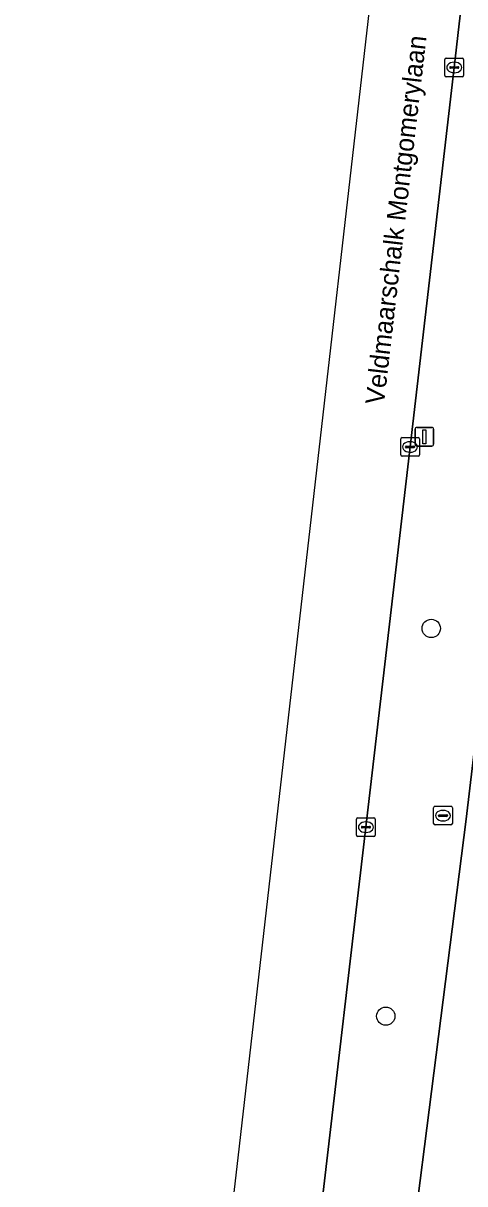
# Model space of a CAD drawing. Extents: x 161241 to 161758, y 384138 to 384885.
# Drawn here: x 161277.3 to 161300.9, y 384572 to 384634 of the extents above; entities that cross this region are included whole.
import ezdxf

# ---------------------------------------------------------------- set-up
doc = ezdxf.new("R2010")
doc.units = 0
for name, color, linetype in [('IMGEO_Berm_groen', 7, 'Continuous'), ('IMGEO_Boom', 7, 'Continuous'), ('IMGEO_Fietspad_gesloten', 7, 'Continuous'), ('IMGEO_Kolk', 7, 'Continuous'), ('IMGEO_Lichtmast', 7, 'Continuous'), ('IMGEO_Openbare_ruimte_label', 7, 'Continuous'), ('IMGEO_OVBaan_gesloten', 7, 'Continuous'), ('IMGEO_Rioolput', 7, 'Continuous')]:
    doc.layers.add(name, color=color, linetype=linetype)

msp = doc.modelspace()

# ---------------------------------------------------------------- linework, layer by layer
at = {"layer": 'IMGEO_Berm_groen'}
msp.add_lwpolyline([(161278.307, 384403.15), (161286.202, 384471.417), (161293.323, 384531.813), (161296.311, 384554.647), (161300.999, 384591.473), (161306.453, 384637.728), (161301.117, 384638.364), (161300.355, 384631.67), (161297.994, 384611.38), (161295.634, 384591.049), (161293.255, 384570.775), (161290.848, 384550.464), (161288.707, 384532.15), (161288.472, 384530.133), (161286.341, 384511.851), (161283.768, 384490.025), (161281.583, 384471.698), (161279.185, 384451.364)], dxfattribs=at)
at = {"layer": 'IMGEO_Boom'}
for centre in [(161299.125, 384601.675), (161296.698, 384580.943)]:
    msp.add_circle(centre, 0.489, dxfattribs=at)
at = {"layer": 'IMGEO_Fietspad_gesloten'}
msp.add_lwpolyline([(161308.263, 384652.525), (161306.453, 384637.728), (161300.999, 384591.473), (161296.311, 384554.647), (161293.323, 384531.813), (161286.202, 384471.417), (161278.307, 384403.15), (161275.866, 384382.258), (161272.845, 384356.399), (161269.542, 384328.133), (161269.524, 384327.978), (161266.559, 384302.554), (161265.412, 384302.67), (161262.065, 384303.024), (161261.777, 384300.445), (161262.272, 384300.399), (161264.329, 384300.231)], dxfattribs=at)
at = {"layer": 'IMGEO_Kolk'}
for p, q in [((161299.854, 384631.244), (161299.854, 384632.096)), ((161299.929, 384632.17), (161300.781, 384632.17)), ((161300.855, 384632.096), (161300.855, 384631.244)), ((161300.113, 384631.664), (161300.113, 384631.676)), ((161300.551, 384631.627), (161300.153, 384631.627)), ((161300.156, 384631.713), (161300.554, 384631.713)), ((161300.342, 384631.95), (161300.367, 384631.95)), ((161300.597, 384631.676), (161300.597, 384631.664)), ((161300.781, 384631.17), (161299.929, 384631.17)), ((161300.365, 384631.39), (161300.34, 384631.39)), ((161297.493, 384610.954), (161297.493, 384611.806)), ((161297.568, 384611.88), (161298.42, 384611.88)), ((161297.981, 384611.66), (161298.006, 384611.66)), ((161298.494, 384611.806), (161298.494, 384610.954)), ((161297.752, 384611.374), (161297.752, 384611.386)), ((161298.19, 384611.337), (161297.792, 384611.337)), ((161297.795, 384611.423), (161298.193, 384611.423)), ((161298.004, 384611.1), (161297.979, 384611.1)), ((161298.236, 384611.386), (161298.236, 384611.374)), ((161298.42, 384610.88), (161297.568, 384610.88)), ((161295.133, 384590.623), (161295.133, 384591.475)), ((161295.208, 384591.549), (161296.06, 384591.549)), ((161295.621, 384591.329), (161295.646, 384591.329)), ((161296.134, 384591.475), (161296.134, 384590.623)), ((161296.06, 384590.549), (161295.208, 384590.549)), ((161295.392, 384591.043), (161295.392, 384591.055)), ((161295.83, 384591.006), (161295.432, 384591.006)), ((161295.435, 384591.092), (161295.833, 384591.092)), ((161295.644, 384590.769), (161295.619, 384590.769)), ((161295.876, 384591.055), (161295.876, 384591.043))]:
    msp.add_line(p, q, dxfattribs=at)
for points in [[(161299.854, 384631.244), (161299.854, 384632.096)], [(161299.929, 384632.17), (161300.781, 384632.17)], [(161300.855, 384632.096), (161300.855, 384631.244)], [(161300.781, 384631.17), (161299.929, 384631.17)], [(161297.493, 384610.954), (161297.493, 384611.806)], [(161297.568, 384611.88), (161298.42, 384611.88)], [(161298.494, 384611.806), (161298.494, 384610.954)], [(161298.42, 384610.88), (161297.568, 384610.88)], [(161295.133, 384590.623), (161295.133, 384591.475)], [(161295.208, 384591.549), (161296.06, 384591.549)], [(161296.134, 384591.475), (161296.134, 384590.623)], [(161296.06, 384590.549), (161295.208, 384590.549)]]:
    msp.add_lwpolyline(points, dxfattribs=at)
for centre, radius, start, end in [((161299.931, 384632.094), 0.0765, 91.55205, 178.44795), ((161299.931, 384632.094), 0.0765, 91.55205, 178.44795), ((161300.779, 384632.094), 0.0765, 1.55205, 88.44795), ((161300.779, 384632.094), 0.0765, 1.55205, 88.44795), ((161300.153, 384631.673), 0.0403, 85.87752, 175.75265), ((161300.15, 384631.663), 0.0366, 178.93798, 274.71019), ((161300.554, 384631.67), 0.043, 264.86636, 352.45326), ((161300.558, 384631.675), 0.0386, 1.73085, 96.63898), ((161299.931, 384631.246), 0.0765, 181.55205, 268.44795), ((161299.931, 384631.246), 0.0765, 181.55205, 268.44795), ((161300.779, 384631.246), 0.0765, 271.55205, 358.44795), ((161300.779, 384631.246), 0.0765, 271.55205, 358.44795), ((161297.57, 384611.804), 0.0765, 91.55205, 178.44795), ((161297.57, 384611.804), 0.0765, 91.55205, 178.44795), ((161298.418, 384611.804), 0.0765, 1.55205, 88.44795), ((161298.418, 384611.804), 0.0765, 1.55205, 88.44795), ((161297.792, 384611.383), 0.0403, 85.87752, 175.75265), ((161297.789, 384611.373), 0.0366, 178.93798, 274.71019), ((161298.193, 384611.38), 0.043, 264.86636, 352.45326), ((161298.197, 384611.385), 0.0386, 1.73085, 96.63898), ((161297.57, 384610.956), 0.0765, 181.55205, 268.44795), ((161297.57, 384610.956), 0.0765, 181.55205, 268.44795), ((161298.418, 384610.956), 0.0765, 271.55205, 358.44795), ((161298.418, 384610.956), 0.0765, 271.55205, 358.44795), ((161295.21, 384591.473), 0.0765, 91.55205, 178.44795), ((161295.21, 384591.473), 0.0765, 91.55205, 178.44795), ((161296.058, 384591.473), 0.0765, 1.55205, 88.44795), ((161296.058, 384591.473), 0.0765, 1.55205, 88.44795), ((161295.21, 384590.625), 0.0765, 181.55205, 268.44795), ((161295.21, 384590.625), 0.0765, 181.55205, 268.44795), ((161295.432, 384591.052), 0.0403, 85.87752, 175.75265), ((161295.429, 384591.042), 0.0366, 178.93798, 274.71019), ((161295.833, 384591.049), 0.043, 264.86636, 352.45326), ((161295.837, 384591.054), 0.0386, 1.73085, 96.63898), ((161296.058, 384590.625), 0.0765, 271.55205, 358.44795), ((161296.058, 384590.625), 0.0765, 271.55205, 358.44795)]:
    msp.add_arc(centre, radius, start, end, dxfattribs=at)
for centre, major_axis, ratio, start_param, end_param in [((161300.341, 384631.67), (-0.387, 0.002), 0.722429, 4.712389, 7.853982), ((161300.366, 384631.67), (-0.39, 0.002), 0.717154, 1.570796, 4.712389), ((161297.98, 384611.38), (-0.387, 0.002), 0.722429, 4.712389, 7.853982), ((161298.005, 384611.38), (-0.39, 0.002), 0.717154, 1.570796, 4.712389), ((161295.62, 384591.049), (-0.387, 0.002), 0.722429, 4.712389, 7.853982), ((161295.645, 384591.049), (-0.39, 0.002), 0.717154, 1.570796, 4.712389)]:
    msp.add_ellipse(centre, major_axis=major_axis, ratio=ratio, start_param=start_param, end_param=end_param, dxfattribs=at)
at = {"layer": 'IMGEO_Lichtmast'}
for p, q in [((161298.261, 384611.525), (161298.261, 384612.325)), ((161298.261, 384612.325), (161298.261, 384611.525)), ((161298.361, 384612.425), (161299.151, 384612.425)), ((161299.151, 384612.425), (161298.361, 384612.425)), ((161299.251, 384612.325), (161299.251, 384611.525)), ((161299.251, 384611.525), (161299.251, 384612.325)), ((161299.151, 384611.425), (161298.361, 384611.425)), ((161298.361, 384611.425), (161299.151, 384611.425))]:
    msp.add_line(p, q, dxfattribs=at)
msp.add_lwpolyline([(161298.681, 384612.3), (161298.831, 384612.3), (161298.831, 384611.55), (161298.681, 384611.55), (161298.681, 384612.3)], dxfattribs=at)
for centre, start, end in [((161298.361, 384612.325), 90, 180), ((161298.361, 384612.325), 90, 180), ((161299.151, 384612.325), 0, 90), ((161299.151, 384612.325), 360, 90), ((161298.361, 384611.525), 180, 270), ((161298.361, 384611.525), 180, 270), ((161299.151, 384611.525), 270, 0), ((161299.151, 384611.525), 270, 0)]:
    msp.add_arc(centre, 0.1, start, end, dxfattribs=at)
at = {"layer": 'IMGEO_OVBaan_gesloten'}
for points in [[(161312.353, 384812.006), (161309.921, 384834.117), (161309.774, 384835.487), (161309.446, 384838.541), (161309.033, 384842.394), (161308.618, 384846.264), (161308.42, 384848.049), (161305.427, 384848.093), (161310.221, 384805.365), (161309.046, 384772.256), (161307.924, 384740.658), (161299.466, 384666.717), (161288.788, 384573.374), (161256.675, 384295.749), (161254.709, 384278.75), (161244.663, 384173.474), (161243.814, 384162.675), (161243.598, 384159.911), (161243.455, 384158.862), (161242.942, 384154.711), (161242.923, 384154.593), (161242.753, 384153.458), (161241.269, 384137.91)], [(161261.738, 384300.096), (161261.777, 384300.445), (161262.065, 384303.024), (161262.902, 384310.522), (161264.916, 384328.431), (161267.197, 384347.869), (161269.457, 384367.164), (161271.789, 384387.356), (161274.112, 384407.478), (161276.721, 384430.069), (161279.185, 384451.364), (161281.583, 384471.698), (161283.768, 384490.025), (161286.341, 384511.851), (161288.472, 384530.133), (161288.707, 384532.15), (161290.848, 384550.464), (161293.255, 384570.775), (161295.634, 384591.049), (161297.994, 384611.38), (161300.355, 384631.67), (161301.117, 384638.364), (161302.766, 384651.987), (161302.856, 384653.145)]]:
    msp.add_lwpolyline(points, dxfattribs=at)
at = {"layer": 'IMGEO_Rioolput'}
for p, q in [((161299.254, 384591.24), (161299.254, 384592.092)), ((161299.329, 384592.166), (161300.181, 384592.166)), ((161299.742, 384591.946), (161299.767, 384591.946)), ((161300.255, 384592.092), (161300.255, 384591.24)), ((161300.181, 384591.166), (161299.329, 384591.166)), ((161299.513, 384591.66), (161299.513, 384591.672)), ((161299.951, 384591.623), (161299.553, 384591.623)), ((161299.556, 384591.709), (161299.954, 384591.709)), ((161299.765, 384591.386), (161299.74, 384591.386)), ((161299.997, 384591.672), (161299.997, 384591.66))]:
    msp.add_line(p, q, dxfattribs=at)
for points in [[(161299.254, 384591.24), (161299.254, 384592.092)], [(161299.329, 384592.166), (161300.181, 384592.166)], [(161300.255, 384592.092), (161300.255, 384591.24)], [(161300.181, 384591.166), (161299.329, 384591.166)]]:
    msp.add_lwpolyline(points, dxfattribs=at)
for centre, radius, start, end in [((161299.331, 384592.09), 0.0765, 91.55205, 178.44795), ((161299.331, 384592.09), 0.0765, 91.55205, 178.44795), ((161300.179, 384592.09), 0.0765, 1.55205, 88.44795), ((161300.179, 384592.09), 0.0765, 1.55205, 88.44795), ((161299.331, 384591.242), 0.0765, 181.55205, 268.44795), ((161299.331, 384591.242), 0.0765, 181.55205, 268.44795), ((161299.553, 384591.669), 0.0403, 85.87752, 175.75265), ((161299.55, 384591.659), 0.0366, 178.93798, 274.71019), ((161299.954, 384591.666), 0.043, 264.86636, 352.45326), ((161299.958, 384591.671), 0.0386, 1.73085, 96.63898), ((161300.179, 384591.242), 0.0765, 271.55205, 358.44795), ((161300.179, 384591.242), 0.0765, 271.55205, 358.44795)]:
    msp.add_arc(centre, radius, start, end, dxfattribs=at)
for centre, major_axis, ratio, start_param, end_param in [((161299.741, 384591.666), (-0.387, 0.002), 0.722429, 4.712389, 7.853982), ((161299.766, 384591.666), (-0.39, 0.002), 0.717154, 1.570796, 4.712389)]:
    msp.add_ellipse(centre, major_axis=major_axis, ratio=ratio, start_param=start_param, end_param=end_param, dxfattribs=at)

# ---------------------------------------------------------------- texts
at = {"layer": 'IMGEO_Openbare_ruimte_label'}
msp.add_text('Veldmaarschalk Montgomerylaan', height=1, rotation=83.39397, dxfattribs=at).set_placement((161296.596, 384613.608))

doc.saveas('drawing.dxf')
